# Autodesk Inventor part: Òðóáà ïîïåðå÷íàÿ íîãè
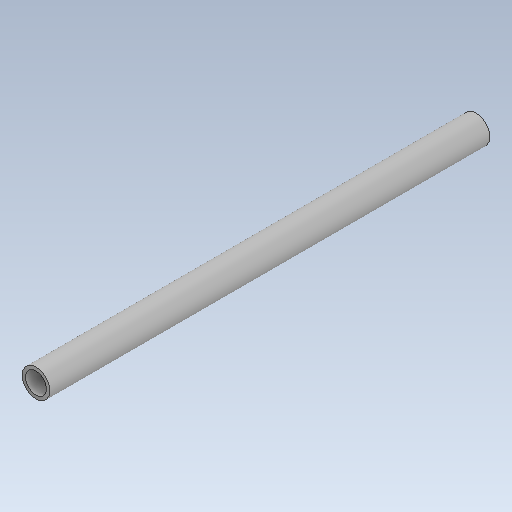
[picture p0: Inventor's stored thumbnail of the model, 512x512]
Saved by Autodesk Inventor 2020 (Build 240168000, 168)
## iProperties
Created: 1900-01
Part Number: Òðóáà ïîïåðå÷íàÿ íîãè
Material: Générique
Document SubType Name: Modeling
Designer: bruno
Density: 1 g/cm^3
Appearance: Par défaut
Author: bruno
Revision Number: ANYUNSPECIFIED
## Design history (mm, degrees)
feature "Base1"
node "Solide1"
